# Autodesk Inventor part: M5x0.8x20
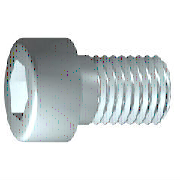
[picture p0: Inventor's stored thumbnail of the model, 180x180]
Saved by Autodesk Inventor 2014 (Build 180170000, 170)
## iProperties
IsCustomPart: 0
Created: 2009-02
Part Number: M5x0.8x20
Material: Steel, Mild
Description: 6각머리 태핑 나사
Document SubType Name: Modeling
Standard: KS B 1003
Designer: KYOUNG IL JANG
Standards Organization: KS
Language: ko-KR
Size Designation: M 5 x 20
Categories: <MemberInstance><Categories><Category DisplayName="조임쇠" InternalName="e4da775c-781d-43d5-af7c-5136215cf5a6" Mnemonic="FSTN"><Category DisplayName="볼트" InternalN
Density: 7.86 g/cm^3
Mass: 4.9629 g
Surface Area: 5.88237 cm^2
Volume: 0.631412 cm^3
Appearance: Metal-Steel
Author: KYOUNG IL JANG
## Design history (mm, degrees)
sketch "스케치1"
  geometry: L1 (-1.167, 0)-(20, 0); L2 (20, 0)-(20, 2.5); L3 (20, 2.5)-(2, 2.5); L4 (2, 2.5)-(1.509, 2.5); L5 (1.509, 2.5)-(0, 2.5); L6 (0, 2.5)-(0, 4.25); L7 (0, 4.25)-(-5, 4.25); L8 (-5, 4.25)-(-5, 2.309); L9 (-5, 2.309)-(-2.5, 2.309); L10 (-2.5, 2.309)-(-1.167, 0); L11 (-10, 0)-(25, 0) reference; L12 (0, -0.85)-(0, 5.1) reference; L13 (2, 2.5)-(0, 2.5)
  constraints: 22 end point, 6 parallel, 2 collinear, 2 perpendicular, 1 horizontal, 1 point on line
  dimensions: "d1" = 18 distance from line of L3.end L2 (= GEL); "d2" = 0.49086 distance of L4.end L3.end (computed from GAL); "d3" = 5 distance between parallel lines of L8 L6 (= KOH); "d4" = 2.5 distance of L8.end L9.end (= INTI); "d5" = 60 deg angle of L10 L1; "d6" = 5 diameter of L3 L1 (= GD); "d7" = 5 diameter of L5 L1 (= BDM); "d8" = 4.6188 diameter of L9 L1 (= 1.1547 x SW); "d9" = 8.5 diameter of L7 L1 (= KOD); "d26" = 20 distance between parallel lines of L12 L2 (= NLG)
revolve "본체" sketch "스케치1" stored, may be unused: angle "d10" = 90 deg
sketch "스케치2"
  geometry: L1 (0, -5.95)-(0, 5.95) reference; L2 (-5.95, 0)-(5.95, 0) reference; L3 (2.309, 0)-(1.155, -2); L4 (1.155, -2)-(-1.155, -2); L5 (-1.155, -2)-(-2.309, 0); L6 (-2.309, 0)-(-1.155, 2); L7 (-1.155, 2)-(1.155, 2); L8 (1.155, 2)-(2.309, 0); 2 further points
  constraints: 12 end point, 1 coincident, 1 horizontal alignment, 1 point on line, 12 other
extrude "슬롯" join sketch "스케치2" stored distance "d11" = 10; taper "d12" = 0 deg
workplane "Work Plane1"
fillet "Fillet2" dims "d30" = 0.1 (= R)
body "Solid1"
fillet "모깎기1" dims "d17" = 0.5 (= RR)
feature "스레드" dims "d13" = 18 (= GEL), "d14" = 0
chamfer "모따기1" distance "d15" = 0.49076 (= -0.5 x SPD + 0.5 x GD); stored, may be unused: second distance "d16" = 0.49076 (= GUL), angle "d27" = 45 deg
other parameters: "GD" = 5 (= NND) [user parameter; used in 2 equation terms], "NLG" = 20 [user parameter; used in 1 equation term], "GEL" = 18 [user parameter; used in 2 equation terms], "KOD" = 8.5 [user parameter; used in 1 equation term], "KOH" = 5 [user parameter; used in 1 equation term], "INTI" = 2.5 [user parameter; used in 1 equation term], "GAL" = 0.49076 (= 0.61345 x PTC) [user parameter; used in 1 equation term], "GUL" = 0.49076 (= 0.61345 x PTC) [user parameter; used in 1 equation term], "BDM" = 5 (= NND) [user parameter; used in 1 equation term], "SW" = 4 [user parameter; used in 2 equation terms], "RR" = 0.5 [user parameter; used in 1 equation term], "SPD" = 4.01848 (= NND - 1.2269 x PTC) [user parameter; used in 1 equation term], "d19" = 0, "d28" = 0, "d29" = 0, "R" = 0.1 [user parameter; used in 1 equation term], "PHH" = 0.2 [user parameter], "GD1" = 4.01848 (= THREADDIA - 1.2269 x PTC) [user parameter], "THREADDIA" = 5 [user parameter; used in 1 equation term], "FAWI" = 45 deg [user parameter], "TPU" = 12.5 (computed from PTC) [user parameter], "PTC" = 0.8 [user parameter; used in 5 equation terms], "NND" = 5 [user parameter; used in 3 equation terms], "TOA" = 30 deg [user parameter], "E0" = 4.62 (= 1.155 x SW) [user parameter]
